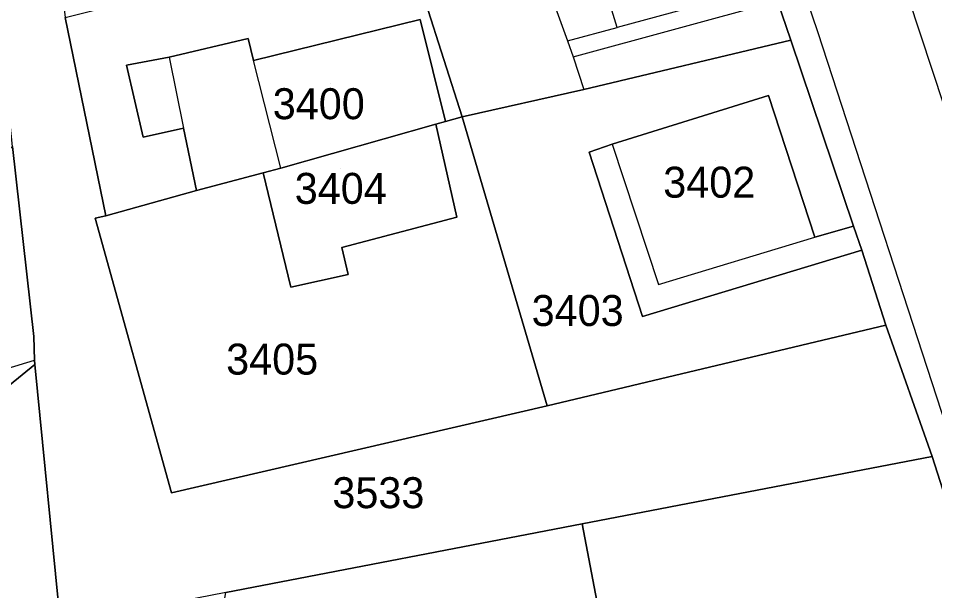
# Model space of a CAD drawing. Extents: x -262657 to -261595, y -1238015 to -1237156.
# Drawn here: x -262030.6 to -261971.4, y -1237612 to -1237575 of the extents above; entities that cross this region are included whole.
import ezdxf

# ---------------------------------------------------------------- set-up
doc = ezdxf.new("R2010")
doc.units = 0
for name, color, linetype in [('body_kn', 7, 'Continuous'), ('kladpar_druhypozemkov', 7, 'Continuous'), ('kladpar_hranice', 7, 'Continuous'), ('kladpar_parcelnecisla', 7, 'Continuous'), ('kladpar_plochy', 7, 'Continuous'), ('zappar_hrandruhpozemk', 7, 'Continuous')]:
    doc.layers.add(name, color=color, linetype=linetype)

msp = doc.modelspace()

# ---------------------------------------------------------------- linework, layer by layer
at = {"layer": 'body_kn'}
for p, q in [((-262004.63, -1237575.07), (-262004.63, -1237575.07)), ((-261991.88, -1237575.6), (-261991.88, -1237575.6)), ((-261991.88, -1237575.6), (-261991.88, -1237575.6)), ((-261978.89, -1237575.95), (-261978.89, -1237575.95)), ((-262015.74, -1237576.3), (-262015.74, -1237576.3)), ((-261995.09, -1237576.45), (-261995.09, -1237576.45)), ((-261995.09, -1237576.45), (-261995.09, -1237576.45)), ((-261980.66, -1237576.41), (-261980.66, -1237576.41)), ((-261980.66, -1237576.41), (-261980.66, -1237576.41)), ((-262023.61, -1237578.02), (-262023.61, -1237578.02)), ((-262020.86, -1237577.51), (-262020.86, -1237577.51)), ((-262020.86, -1237577.51), (-262020.86, -1237577.51)), ((-262015.39, -1237577.73), (-262015.39, -1237577.73)), ((-261994.73, -1237577.5), (-261994.73, -1237577.5)), ((-261994.73, -1237577.5), (-261994.73, -1237577.5)), ((-261994.05, -1237579.6), (-261994.05, -1237579.6)), ((-261982.1, -1237580), (-261982.1, -1237580)), ((-262001.91, -1237581.37), (-262001.91, -1237581.37)), ((-262019.92, -1237582.1), (-262019.92, -1237582.1)), ((-262003.61, -1237581.85), (-262003.61, -1237581.85)), ((-262003.61, -1237581.85), (-262003.61, -1237581.85)), ((-262002.98, -1237581.67), (-262002.98, -1237581.67)), ((-262022.53, -1237582.68), (-262022.53, -1237582.68)), ((-261992.21, -1237583.14), (-261992.21, -1237583.14)), ((-261992.21, -1237583.14), (-261992.21, -1237583.14)), ((-261993.69, -1237583.65), (-261993.69, -1237583.65)), ((-262014.78, -1237584.99), (-262014.78, -1237584.99)), ((-262014.78, -1237584.99), (-262014.78, -1237584.99)), ((-262013.64, -1237584.69), (-262013.64, -1237584.69)), ((-262013.64, -1237584.69), (-262013.64, -1237584.69)), ((-262019.09, -1237586.12), (-262019.09, -1237586.12)), ((-262025.63, -1237587.92), (-262025.63, -1237587.92)), ((-262024.94, -1237587.76), (-262024.94, -1237587.76)), ((-262024.94, -1237587.76), (-262024.94, -1237587.76)), ((-262002.26, -1237587.85), (-262002.26, -1237587.85)), ((-261976.61, -1237588.43), (-261976.61, -1237588.43)), ((-261976.61, -1237588.43), (-261976.61, -1237588.43)), ((-261979.1, -1237589.15), (-261979.1, -1237589.15)), ((-262009.7, -1237589.81), (-262009.7, -1237589.81)), ((-261976.08, -1237589.98), (-261976.08, -1237589.98)), ((-262009.29, -1237591.56), (-262009.29, -1237591.56)), ((-261989.22, -1237592.21), (-261989.22, -1237592.21)), ((-262012.98, -1237592.38), (-262012.98, -1237592.38)), ((-261990.26, -1237594.26), (-261990.26, -1237594.26)), ((-261974.52, -1237594.83), (-261974.52, -1237594.83)), ((-262029.61, -1237595.57), (-262029.61, -1237595.57)), ((-262029.55, -1237597.08), (-262029.55, -1237597.08)), ((-262029.54, -1237597.37), (-262029.54, -1237597.37)), ((-261996.42, -1237600.03), (-261996.42, -1237600.03)), ((-261971.52, -1237603.32), (-261971.52, -1237603.32)), ((-261971.52, -1237603.32), (-261971.52, -1237603.32)), ((-262020.7, -1237605.65), (-262020.7, -1237605.65)), ((-261994.15, -1237607.67), (-261994.15, -1237607.67))]:
    msp.add_line(p, q, dxfattribs=at)
at = {"layer": 'kladpar_druhypozemkov'}
for p, q in [((-262010.45, -1237579.24), (-262010.45, -1237579.24)), ((-261985.51, -1237584.17), (-261985.51, -1237584.17)), ((-262009.77, -1237584.73), (-262009.77, -1237584.73)), ((-261993.89, -1237593.15), (-261993.89, -1237593.15)), ((-262013.78, -1237596.44), (-262013.78, -1237596.44)), ((-262005.91, -1237604.77), (-262005.91, -1237604.77))]:
    msp.add_line(p, q, dxfattribs=at)
at = {"layer": 'kladpar_hranice'}
for points in [[(-262040.84, -1237542.49), (-262032.96, -1237542.94), (-262029.86, -1237555.24), (-262029.25, -1237560.87), (-262027.58, -1237574.94), (-262024.94, -1237587.76), (-262025.63, -1237587.92), (-262020.7, -1237605.65), (-261996.42, -1237600.03), (-261974.52, -1237594.83), (-261971.52, -1237603.32), (-261994.15, -1237607.67), (-262017.2, -1237612.1), (-262026.45, -1237613.9), (-262027.87, -1237614.17), (-262029.54, -1237597.37), (-262029.55, -1237597.08), (-262029.61, -1237595.57), (-262030.98, -1237583.29), (-262031.65, -1237576.78), (-262032.5, -1237567.16), (-262033.04, -1237561.99), (-262033.72, -1237554.19), (-262040.84, -1237542.49)], [(-261963.49, -1237628.42), (-261971.52, -1237603.32), (-261974.52, -1237594.83), (-261976.08, -1237589.98), (-261976.61, -1237588.43), (-261980.66, -1237576.41), (-261981.52, -1237573.9), (-261981.87, -1237572.78), (-261984.6, -1237564.52), (-261986.48, -1237558.8), (-261989.09, -1237551.41), (-261989.35, -1237550.17), (-261991.63, -1237542.33)], [(-261984.6, -1237564.52), (-261981.87, -1237572.78), (-261981.52, -1237573.9), (-261980.66, -1237576.41), (-261994.05, -1237579.6), (-262001.91, -1237581.37), (-262004.29, -1237573.95), (-262005.82, -1237569.51), (-261996.09, -1237567.25), (-261994.26, -1237566.81), (-261986.28, -1237564.88), (-261984.6, -1237564.52)], [(-262024.94, -1237587.76), (-262027.58, -1237574.94), (-262005.82, -1237569.51), (-262004.29, -1237573.95), (-262001.91, -1237581.37), (-262002.98, -1237581.67), (-262004.63, -1237575.07), (-262015.39, -1237577.73), (-262015.74, -1237576.3), (-262020.86, -1237577.51), (-262023.61, -1237578.02), (-262022.53, -1237582.68), (-262019.92, -1237582.1), (-262019.09, -1237586.12), (-262024.94, -1237587.76)], [(-262014.78, -1237584.99), (-262019.09, -1237586.12), (-262019.92, -1237582.1), (-262022.53, -1237582.68), (-262023.61, -1237578.02), (-262020.86, -1237577.51), (-262015.74, -1237576.3), (-262015.39, -1237577.73), (-262004.63, -1237575.07), (-262002.98, -1237581.67), (-262003.61, -1237581.85), (-262013.64, -1237584.69), (-262014.78, -1237584.99)], [(-261980.66, -1237576.41), (-261976.61, -1237588.43), (-261979.1, -1237589.15), (-261982.1, -1237580), (-261992.21, -1237583.14), (-261993.69, -1237583.65), (-261990.26, -1237594.26), (-261976.08, -1237589.98), (-261974.52, -1237594.83), (-261996.42, -1237600.03), (-262001.91, -1237581.37), (-261994.05, -1237579.6), (-261980.66, -1237576.41)], [(-261976.61, -1237588.43), (-261976.08, -1237589.98), (-261990.26, -1237594.26), (-261993.69, -1237583.65), (-261992.21, -1237583.14), (-261982.1, -1237580), (-261979.1, -1237589.15), (-261976.61, -1237588.43)], [(-262003.61, -1237581.85), (-262002.98, -1237581.67), (-262001.91, -1237581.37), (-261996.42, -1237600.03), (-262020.7, -1237605.65), (-262025.63, -1237587.92), (-262024.94, -1237587.76), (-262019.09, -1237586.12), (-262014.78, -1237584.99), (-262012.98, -1237592.38), (-262009.29, -1237591.56), (-262009.7, -1237589.81), (-262002.26, -1237587.85), (-262003.61, -1237581.85)], [(-262014.78, -1237584.99), (-262013.64, -1237584.69), (-262003.61, -1237581.85), (-262002.26, -1237587.85), (-262009.7, -1237589.81), (-262009.29, -1237591.56), (-262012.98, -1237592.38), (-262014.78, -1237584.99)], [(-262030.98, -1237583.29), (-262029.61, -1237595.57), (-262029.55, -1237597.08), (-262029.54, -1237597.37), (-262043.72, -1237608.92), (-262053.55, -1237601.16), (-262044.22, -1237593.78), (-262043.47, -1237593.19), (-262041.07, -1237591.29), (-262040.41, -1237590.77), (-262030.98, -1237583.29)], [(-262043.72, -1237608.92), (-262029.54, -1237597.37), (-262027.87, -1237614.17), (-262029.06, -1237615.25), (-262030.78, -1237613.12), (-262033.66, -1237615.13), (-262043.72, -1237608.92)], [(-261971.52, -1237603.32), (-261963.49, -1237628.42), (-261973.11, -1237629.45), (-261987.81, -1237630.03), (-261988.77, -1237624.81), (-261990.82, -1237625.19), (-261994.15, -1237607.67), (-261971.52, -1237603.32)], [(-262019, -1237622.74), (-262017.2, -1237612.1), (-261994.15, -1237607.67), (-261990.82, -1237625.19), (-261988.77, -1237624.81), (-261987.81, -1237630.03), (-261990.01, -1237630.12), (-262007.2, -1237630.99), (-262024.39, -1237631.76), (-262025.07, -1237625.9), (-262019, -1237622.74)]]:
    msp.add_lwpolyline(points, dxfattribs=at)
at = {"layer": 'kladpar_plochy'}
for points in [[(-262040.84, -1237542.49), (-262032.96, -1237542.94), (-262029.86, -1237555.24), (-262029.25, -1237560.87), (-262027.58, -1237574.94), (-262024.94, -1237587.76), (-262025.63, -1237587.92), (-262020.7, -1237605.65), (-261996.42, -1237600.03), (-261974.52, -1237594.83), (-261971.52, -1237603.32), (-261994.15, -1237607.67), (-262017.2, -1237612.1), (-262026.45, -1237613.9), (-262027.87, -1237614.17), (-262029.54, -1237597.37), (-262029.55, -1237597.08), (-262029.61, -1237595.57), (-262030.98, -1237583.29), (-262031.65, -1237576.78), (-262032.5, -1237567.16), (-262033.04, -1237561.99), (-262033.72, -1237554.19)], [(-261984.6, -1237564.52), (-261981.87, -1237572.78), (-261981.52, -1237573.9), (-261980.66, -1237576.41), (-261994.05, -1237579.6), (-262001.91, -1237581.37), (-262004.29, -1237573.95), (-262005.82, -1237569.51), (-261996.09, -1237567.25), (-261994.26, -1237566.81), (-261986.28, -1237564.88)], [(-262024.94, -1237587.76), (-262027.58, -1237574.94), (-262005.82, -1237569.51), (-262004.29, -1237573.95), (-262001.91, -1237581.37), (-262002.98, -1237581.67), (-262004.63, -1237575.07), (-262015.39, -1237577.73), (-262015.74, -1237576.3), (-262020.86, -1237577.51), (-262023.61, -1237578.02), (-262022.53, -1237582.68), (-262019.92, -1237582.1), (-262019.09, -1237586.12)], [(-262014.78, -1237584.99), (-262019.09, -1237586.12), (-262019.92, -1237582.1), (-262022.53, -1237582.68), (-262023.61, -1237578.02), (-262020.86, -1237577.51), (-262015.74, -1237576.3), (-262015.39, -1237577.73), (-262004.63, -1237575.07), (-262002.98, -1237581.67), (-262003.61, -1237581.85), (-262013.64, -1237584.69)], [(-261980.66, -1237576.41), (-261976.61, -1237588.43), (-261979.1, -1237589.15), (-261982.1, -1237580), (-261992.21, -1237583.14), (-261993.69, -1237583.65), (-261990.26, -1237594.26), (-261976.08, -1237589.98), (-261974.52, -1237594.83), (-261996.42, -1237600.03), (-262001.91, -1237581.37), (-261994.05, -1237579.6)], [(-261976.61, -1237588.43), (-261976.08, -1237589.98), (-261990.26, -1237594.26), (-261993.69, -1237583.65), (-261992.21, -1237583.14), (-261982.1, -1237580), (-261979.1, -1237589.15)], [(-262003.61, -1237581.85), (-262002.98, -1237581.67), (-262001.91, -1237581.37), (-261996.42, -1237600.03), (-262020.7, -1237605.65), (-262025.63, -1237587.92), (-262024.94, -1237587.76), (-262019.09, -1237586.12), (-262014.78, -1237584.99), (-262012.98, -1237592.38), (-262009.29, -1237591.56), (-262009.7, -1237589.81), (-262002.26, -1237587.85)], [(-262014.78, -1237584.99), (-262013.64, -1237584.69), (-262003.61, -1237581.85), (-262002.26, -1237587.85), (-262009.7, -1237589.81), (-262009.29, -1237591.56), (-262012.98, -1237592.38)], [(-262030.98, -1237583.29), (-262029.61, -1237595.57), (-262029.55, -1237597.08), (-262029.54, -1237597.37), (-262043.72, -1237608.92), (-262053.55, -1237601.16), (-262044.22, -1237593.78), (-262043.47, -1237593.19), (-262041.07, -1237591.29), (-262040.41, -1237590.77)], [(-262043.72, -1237608.92), (-262029.54, -1237597.37), (-262027.87, -1237614.17), (-262029.06, -1237615.25), (-262030.78, -1237613.12), (-262033.66, -1237615.13)], [(-261971.52, -1237603.32), (-261963.49, -1237628.42), (-261973.11, -1237629.45), (-261987.81, -1237630.03), (-261988.77, -1237624.81), (-261990.82, -1237625.19), (-261994.15, -1237607.67)], [(-262019, -1237622.74), (-262017.2, -1237612.1), (-261994.15, -1237607.67), (-261990.82, -1237625.19), (-261988.77, -1237624.81), (-261987.81, -1237630.03), (-261990.01, -1237630.12), (-262007.2, -1237630.99), (-262024.39, -1237631.76), (-262025.07, -1237625.9)]]:
    msp.add_lwpolyline(points, close=True, dxfattribs=at)
msp.add_lwpolyline([(-261963.49, -1237628.42), (-261971.52, -1237603.32), (-261974.52, -1237594.83), (-261976.08, -1237589.98), (-261976.61, -1237588.43), (-261980.66, -1237576.41), (-261981.52, -1237573.9), (-261981.87, -1237572.78), (-261984.6, -1237564.52), (-261986.48, -1237558.8), (-261989.09, -1237551.41), (-261989.35, -1237550.17), (-261991.63, -1237542.33)], dxfattribs=at)
at = {"layer": 'zappar_hrandruhpozemk'}
for p, q in [((-261978.89, -1237575.95), (-261986.21, -1237554.52)), ((-261976.86, -1237562.12), (-261952.08, -1237637.52)), ((-261994.73, -1237577.5), (-261981.52, -1237573.9)), ((-261995.09, -1237576.45), (-261991.88, -1237575.6)), ((-261957.8, -1237640.72), (-261978.89, -1237575.95)), ((-262020.86, -1237577.51), (-262019.92, -1237582.1)), ((-262013.64, -1237584.69), (-262015.39, -1237577.73)), ((-261992.21, -1237583.14), (-261989.22, -1237592.21)), ((-261989.22, -1237592.21), (-261979.1, -1237589.15))]:
    msp.add_line(p, q, dxfattribs=at)
for points in [[(-261986.28, -1237564.88), (-261984, -1237573.44), (-261991.88, -1237575.6)], [(-261991.88, -1237575.6), (-261993.09, -1237571.66), (-261994.66, -1237571.98)], [(-261996.62, -1237572.23), (-261995.09, -1237576.45), (-261994.73, -1237577.5), (-261994.05, -1237579.6)], [(-262037.81, -1237600.51), (-262036.62, -1237599.83), (-262034.39, -1237598.56), (-262029.55, -1237597.08)]]:
    msp.add_lwpolyline(points, dxfattribs=at)

# ---------------------------------------------------------------- texts
at = {"layer": 'kladpar_parcelnecisla'}
for s, p in [('3400', (-262014.155, -1237581.52)), ('3402', (-261988.91, -1237586.59)), ('3404', (-262012.734, -1237586.99)), ('3403', (-261997.416, -1237594.88)), ('3405', (-262017.169, -1237598.02)), ('3533', (-262010.302, -1237606.65))]:
    msp.add_text(s, height=2, dxfattribs=at).set_placement(p)

doc.saveas('drawing.dxf')
